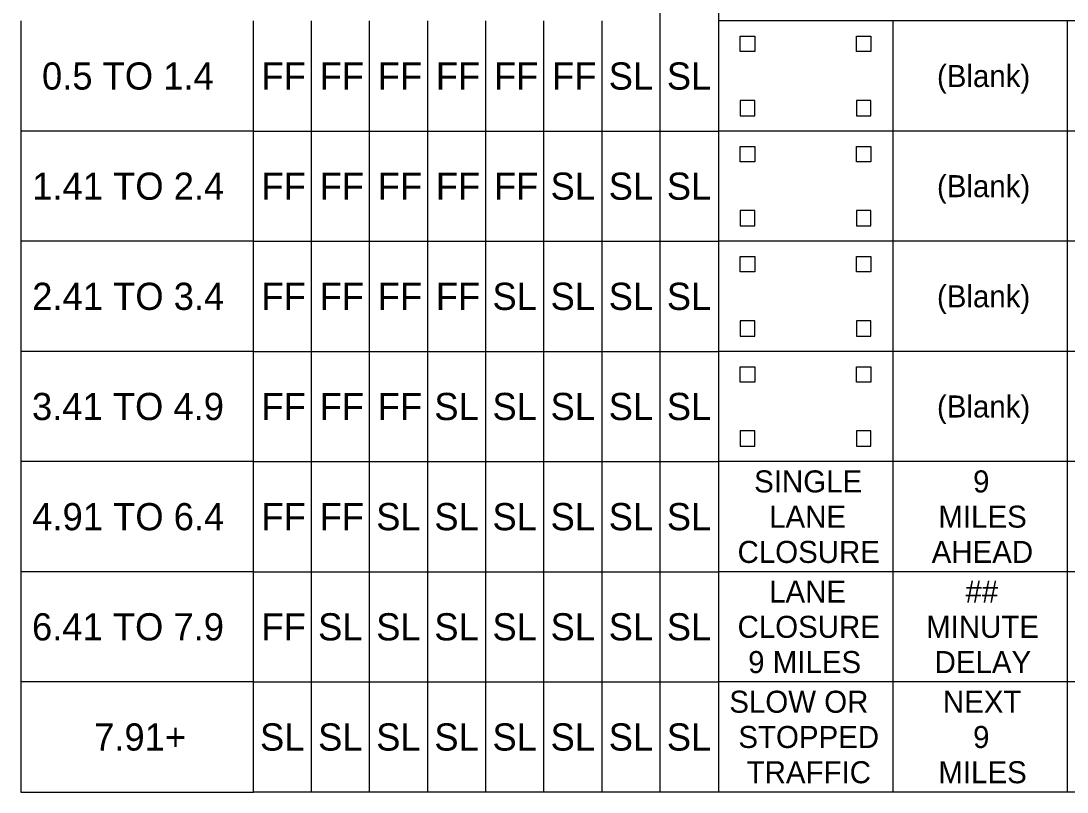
# Model space of a CAD drawing. Extents: x 99999.1 to 100055.7, y 99995 to 100017.5.
# Drawn here: x 100004.329 to 100007.417, y 100001.966 to 100004.241 of the extents above; entities that cross this region are included whole.
import ezdxf

# ---------------------------------------------------------------- set-up
doc = ezdxf.new("R2010")
doc.units = 0
doc.layers.add('TR_WZ_WorkZoneDetails', color=7, linetype='Continuous')
doc.layers.add('TR_WZ_WorkZoneTextCurrent', color=7, linetype='Continuous')

msp = doc.modelspace()

# ---------------------------------------------------------------- linework, layer by layer
at = {"layer": 'TR_WZ_WorkZoneDetails'}
for p, q in [((100004.3292, 100004.2408), (100004.3292, 100003.9158)), ((100005.0153, 100003.9158), (100005.0153, 100004.2408)), ((100005.1868, 100003.9158), (100005.1868, 100004.2408)), ((100005.1868, 100003.9158), (100005.1868, 100004.2408)), ((100005.3583, 100003.9158), (100005.3583, 100004.2408)), ((100005.3583, 100003.9158), (100005.3583, 100004.2408)), ((100005.5299, 100003.9158), (100005.5299, 100004.2408)), ((100005.7014, 100003.9158), (100005.7014, 100004.2408)), ((100005.8729, 100003.9158), (100005.8729, 100004.2408)), ((100006.0444, 100003.9158), (100006.0444, 100004.2408)), ((100006.216, 100003.9158), (100006.216, 100004.2408)), ((100006.3875, 100004.2408), (100006.3875, 100003.9158)), ((100007.4167, 100004.2408), (100006.3875, 100004.2408)), ((100006.9021, 100004.2408), (100006.9021, 100003.9158)), ((100008.4458, 100004.2408), (100007.4167, 100004.2408)), ((100007.4167, 100004.2408), (100007.4167, 100003.9158)), ((100005.0153, 100003.9158), (100004.3292, 100003.9158)), ((100004.3292, 100003.9158), (100004.3292, 100003.5908)), ((100005.0153, 100003.5908), (100005.0153, 100003.9158)), ((100005.0153, 100003.9158), (100005.1868, 100003.9158)), ((100005.1868, 100003.9158), (100005.3583, 100003.9158)), ((100005.1868, 100003.5908), (100005.1868, 100003.9158)), ((100005.1868, 100003.5908), (100005.1868, 100003.9158)), ((100005.3583, 100003.5908), (100005.3583, 100003.9158)), ((100005.3583, 100003.9158), (100005.5299, 100003.9158)), ((100005.3583, 100003.5908), (100005.3583, 100003.9158)), ((100005.5299, 100003.5908), (100005.5299, 100003.9158)), ((100005.5299, 100003.9158), (100005.7014, 100003.9158)), ((100005.7014, 100003.5908), (100005.7014, 100003.9158)), ((100005.7014, 100003.9158), (100005.8729, 100003.9158)), ((100005.8729, 100003.5908), (100005.8729, 100003.9158)), ((100005.8729, 100003.9158), (100006.0444, 100003.9158)), ((100006.0444, 100003.5908), (100006.0444, 100003.9158)), ((100006.0444, 100003.9158), (100006.216, 100003.9158)), ((100006.216, 100003.5908), (100006.216, 100003.9158)), ((100006.216, 100003.9158), (100006.3875, 100003.9158)), ((100006.3875, 100003.9158), (100006.3875, 100003.5908)), ((100007.4167, 100003.9158), (100006.3875, 100003.9158)), ((100006.9021, 100003.9158), (100006.9021, 100003.5908)), ((100008.4458, 100003.9158), (100007.4167, 100003.9158)), ((100007.4167, 100003.9158), (100007.4167, 100003.5908)), ((100005.0153, 100003.5908), (100004.3292, 100003.5908)), ((100004.3292, 100003.5908), (100004.3292, 100003.2658)), ((100005.0153, 100003.2658), (100005.0153, 100003.5908)), ((100005.0153, 100003.5908), (100005.1868, 100003.5908)), ((100005.1868, 100003.5908), (100005.3583, 100003.5908)), ((100005.1868, 100003.2658), (100005.1868, 100003.5908)), ((100005.1868, 100003.2658), (100005.1868, 100003.5908)), ((100005.3583, 100003.2658), (100005.3583, 100003.5908)), ((100005.3583, 100003.5908), (100005.5299, 100003.5908)), ((100005.3583, 100003.2658), (100005.3583, 100003.5908)), ((100005.5299, 100003.2658), (100005.5299, 100003.5908)), ((100005.5299, 100003.5908), (100005.7014, 100003.5908)), ((100005.7014, 100003.2658), (100005.7014, 100003.5908)), ((100005.7014, 100003.5908), (100005.8729, 100003.5908)), ((100005.8729, 100003.2658), (100005.8729, 100003.5908)), ((100005.8729, 100003.5908), (100006.0444, 100003.5908)), ((100006.0444, 100003.2658), (100006.0444, 100003.5908)), ((100006.0444, 100003.5908), (100006.216, 100003.5908)), ((100006.216, 100003.2658), (100006.216, 100003.5908)), ((100006.216, 100003.5908), (100006.3875, 100003.5908)), ((100006.3875, 100003.5908), (100006.3875, 100003.2658)), ((100007.4167, 100003.5908), (100006.3875, 100003.5908)), ((100006.9021, 100003.5908), (100006.9021, 100003.2658)), ((100008.4458, 100003.5908), (100007.4167, 100003.5908)), ((100007.4167, 100003.5908), (100007.4167, 100003.2658)), ((100005.0153, 100003.2658), (100004.3292, 100003.2658)), ((100004.3292, 100003.2658), (100004.3292, 100002.9408)), ((100005.0153, 100002.9408), (100005.0153, 100003.2658)), ((100005.0153, 100003.2658), (100005.1868, 100003.2658)), ((100005.1868, 100003.2658), (100005.3583, 100003.2658)), ((100005.1868, 100002.9408), (100005.1868, 100003.2658)), ((100005.1868, 100002.9408), (100005.1868, 100003.2658)), ((100005.3583, 100002.9408), (100005.3583, 100003.2658)), ((100005.3583, 100003.2658), (100005.5299, 100003.2658)), ((100005.3583, 100002.9408), (100005.3583, 100003.2658)), ((100005.5299, 100002.9408), (100005.5299, 100003.2658)), ((100005.5299, 100003.2658), (100005.7014, 100003.2658)), ((100005.7014, 100002.9408), (100005.7014, 100003.2658)), ((100005.7014, 100003.2658), (100005.8729, 100003.2658)), ((100005.8729, 100002.9408), (100005.8729, 100003.2658)), ((100005.8729, 100003.2658), (100006.0444, 100003.2658)), ((100006.0444, 100002.9408), (100006.0444, 100003.2658)), ((100006.0444, 100003.2658), (100006.216, 100003.2658)), ((100006.216, 100002.9408), (100006.216, 100003.2658)), ((100006.216, 100003.2658), (100006.3875, 100003.2658)), ((100006.3875, 100003.2658), (100006.3875, 100002.9408)), ((100007.4167, 100003.2658), (100006.3875, 100003.2658)), ((100006.9021, 100003.2658), (100006.9021, 100002.9408)), ((100008.4458, 100003.2658), (100007.4167, 100003.2658)), ((100007.4167, 100003.2658), (100007.4167, 100002.9408)), ((100005.0153, 100002.9408), (100004.3292, 100002.9408)), ((100004.3292, 100002.9408), (100004.3292, 100002.6158)), ((100005.0153, 100002.6158), (100005.0153, 100002.9408)), ((100005.0153, 100002.9408), (100005.1868, 100002.9408)), ((100005.1868, 100002.9408), (100005.3583, 100002.9408)), ((100005.1868, 100002.6158), (100005.1868, 100002.9408)), ((100005.1868, 100002.6158), (100005.1868, 100002.9408)), ((100005.3583, 100002.6158), (100005.3583, 100002.9408)), ((100005.3583, 100002.9408), (100005.5299, 100002.9408)), ((100005.3583, 100002.6158), (100005.3583, 100002.9408)), ((100005.5299, 100002.6158), (100005.5299, 100002.9408)), ((100005.5299, 100002.9408), (100005.7014, 100002.9408)), ((100005.7014, 100002.6158), (100005.7014, 100002.9408)), ((100005.7014, 100002.9408), (100005.8729, 100002.9408)), ((100005.8729, 100002.6158), (100005.8729, 100002.9408)), ((100005.8729, 100002.9408), (100006.0444, 100002.9408)), ((100006.0444, 100002.6158), (100006.0444, 100002.9408)), ((100006.0444, 100002.9408), (100006.216, 100002.9408)), ((100006.216, 100002.6158), (100006.216, 100002.9408)), ((100006.216, 100002.9408), (100006.3875, 100002.9408)), ((100006.3875, 100002.9408), (100006.3875, 100002.6158)), ((100007.4167, 100002.9408), (100006.3875, 100002.9408)), ((100006.9021, 100002.9408), (100006.9021, 100002.6158)), ((100008.4458, 100002.9408), (100007.4167, 100002.9408)), ((100007.4167, 100002.9408), (100007.4167, 100002.6158)), ((100005.0153, 100002.6158), (100004.3292, 100002.6158)), ((100005.0153, 100002.6158), (100004.3292, 100002.6158)), ((100004.3292, 100002.6158), (100004.3292, 100002.2908)), ((100005.0153, 100002.6158), (100005.1868, 100002.6158)), ((100005.0153, 100002.2908), (100005.0153, 100002.6158)), ((100005.0153, 100002.6158), (100005.1868, 100002.6158)), ((100005.1868, 100002.6158), (100005.3583, 100002.6158)), ((100005.1868, 100002.6158), (100005.3583, 100002.6158)), ((100005.1868, 100002.2908), (100005.1868, 100002.6158)), ((100005.1868, 100002.2908), (100005.1868, 100002.6158)), ((100005.3583, 100002.6158), (100005.5299, 100002.6158)), ((100005.3583, 100002.2908), (100005.3583, 100002.6158)), ((100005.3583, 100002.6158), (100005.5299, 100002.6158)), ((100005.3583, 100002.2908), (100005.3583, 100002.6158)), ((100005.5299, 100002.6158), (100005.7014, 100002.6158)), ((100005.5299, 100002.2908), (100005.5299, 100002.6158)), ((100005.5299, 100002.6158), (100005.7014, 100002.6158)), ((100005.7014, 100002.6158), (100005.8729, 100002.6158)), ((100005.7014, 100002.2908), (100005.7014, 100002.6158)), ((100005.7014, 100002.6158), (100005.8729, 100002.6158)), ((100005.8729, 100002.6158), (100006.0444, 100002.6158)), ((100005.8729, 100002.2908), (100005.8729, 100002.6158)), ((100005.8729, 100002.6158), (100006.0444, 100002.6158)), ((100006.0444, 100002.6158), (100006.216, 100002.6158)), ((100006.0444, 100002.2908), (100006.0444, 100002.6158)), ((100006.0444, 100002.6158), (100006.216, 100002.6158)), ((100006.216, 100002.6158), (100006.3875, 100002.6158)), ((100006.216, 100002.2908), (100006.216, 100002.6158)), ((100006.216, 100002.6158), (100006.3875, 100002.6158)), ((100007.4167, 100002.6158), (100006.3875, 100002.6158)), ((100006.3875, 100002.6158), (100006.3875, 100002.2908)), ((100007.4167, 100002.6158), (100006.3875, 100002.6158)), ((100006.9021, 100002.6158), (100006.9021, 100002.2908)), ((100008.4458, 100002.6158), (100007.4167, 100002.6158)), ((100008.4458, 100002.6158), (100007.4167, 100002.6158)), ((100007.4167, 100002.6158), (100007.4167, 100002.2908)), ((100004.3292, 100002.2908), (100004.3292, 100001.9658)), ((100005.0153, 100002.2908), (100004.3292, 100002.2908)), ((100005.0153, 100001.9658), (100005.0153, 100002.2908)), ((100005.0153, 100002.2908), (100005.1868, 100002.2908)), ((100005.1868, 100001.9658), (100005.1868, 100002.2908)), ((100005.1868, 100001.9658), (100005.1868, 100002.2908)), ((100005.1868, 100002.2908), (100005.3583, 100002.2908)), ((100005.3583, 100001.9658), (100005.3583, 100002.2908)), ((100005.3583, 100001.9658), (100005.3583, 100002.2908)), ((100005.3583, 100002.2908), (100005.5299, 100002.2908)), ((100005.5299, 100001.9658), (100005.5299, 100002.2908)), ((100005.5299, 100002.2908), (100005.7014, 100002.2908)), ((100005.7014, 100001.9658), (100005.7014, 100002.2908)), ((100005.7014, 100002.2908), (100005.8729, 100002.2908)), ((100005.8729, 100001.9658), (100005.8729, 100002.2908)), ((100005.8729, 100002.2908), (100006.0444, 100002.2908)), ((100006.0444, 100001.9658), (100006.0444, 100002.2908)), ((100006.0444, 100002.2908), (100006.216, 100002.2908)), ((100006.216, 100001.9658), (100006.216, 100002.2908)), ((100006.216, 100002.2908), (100006.3875, 100002.2908)), ((100006.3875, 100002.2908), (100006.3875, 100001.9658)), ((100007.4167, 100002.2908), (100006.3875, 100002.2908)), ((100006.9021, 100002.2908), (100006.9021, 100001.9658)), ((100007.4167, 100002.2908), (100007.4167, 100001.9658)), ((100008.4458, 100002.2908), (100007.4167, 100002.2908)), ((100004.3292, 100001.9658), (100005.0153, 100001.9658)), ((100005.1868, 100001.9658), (100005.0153, 100001.9658)), ((100005.3583, 100001.9658), (100005.1868, 100001.9658)), ((100005.5299, 100001.9658), (100005.3583, 100001.9658)), ((100005.7014, 100001.9658), (100005.5299, 100001.9658)), ((100005.8729, 100001.9658), (100005.7014, 100001.9658)), ((100006.0444, 100001.9658), (100005.8729, 100001.9658)), ((100006.216, 100001.9658), (100006.0444, 100001.9658)), ((100006.3875, 100001.9658), (100006.216, 100001.9658)), ((100007.4167, 100001.9658), (100006.3875, 100001.9658)), ((100008.4458, 100001.9658), (100007.4167, 100001.9658))]:
    msp.add_line(p, q, dxfattribs=at)
msp.add_lwpolyline([(100006.216, 100004.8908), (100006.3875, 100004.8908), (100006.3875, 100001.9658), (100006.216, 100001.9658)], close=True, dxfattribs=at)
at = {"layer": 'TR_WZ_WorkZoneTextCurrent'}
for points in [[(100006.4518, 100004.1956), (100006.4947, 100004.1956), (100006.4947, 100004.1505), (100006.4518, 100004.1505)], [(100006.7949, 100004.1956), (100006.8378, 100004.1956), (100006.8378, 100004.1505), (100006.7949, 100004.1505)], [(100006.4518, 100003.9609), (100006.4947, 100003.9609), (100006.4947, 100004.0061), (100006.4518, 100004.0061)], [(100006.7949, 100003.9609), (100006.8378, 100003.9609), (100006.8378, 100004.0061), (100006.7949, 100004.0061)], [(100006.4518, 100003.8706), (100006.4947, 100003.8706), (100006.4947, 100003.8255), (100006.4518, 100003.8255)], [(100006.7949, 100003.8706), (100006.8378, 100003.8706), (100006.8378, 100003.8255), (100006.7949, 100003.8255)], [(100006.4518, 100003.6359), (100006.4947, 100003.6359), (100006.4947, 100003.6811), (100006.4518, 100003.6811)], [(100006.7949, 100003.6359), (100006.8378, 100003.6359), (100006.8378, 100003.6811), (100006.7949, 100003.6811)], [(100006.4518, 100003.5456), (100006.4947, 100003.5456), (100006.4947, 100003.5005), (100006.4518, 100003.5005)], [(100006.7949, 100003.5456), (100006.8378, 100003.5456), (100006.8378, 100003.5005), (100006.7949, 100003.5005)], [(100006.4518, 100003.3109), (100006.4947, 100003.3109), (100006.4947, 100003.3561), (100006.4518, 100003.3561)], [(100006.7949, 100003.3109), (100006.8378, 100003.3109), (100006.8378, 100003.3561), (100006.7949, 100003.3561)], [(100006.4518, 100003.2206), (100006.4947, 100003.2206), (100006.4947, 100003.1755), (100006.4518, 100003.1755)], [(100006.7949, 100003.2206), (100006.8378, 100003.2206), (100006.8378, 100003.1755), (100006.7949, 100003.1755)], [(100006.4518, 100002.9859), (100006.4947, 100002.9859), (100006.4947, 100003.0311), (100006.4518, 100003.0311)], [(100006.7949, 100002.9859), (100006.8378, 100002.9859), (100006.8378, 100003.0311), (100006.7949, 100003.0311)]]:
    msp.add_lwpolyline(points, close=True, dxfattribs=at)

# ---------------------------------------------------------------- texts
for s, height, p in [('0.5 TO 1.4', 0.08025, (100004.3913, 100004.0382)), ('FF', 0.08025, (100005.039, 100004.0382)), ('FF', 0.08025, (100005.2105, 100004.0382)), ('FF', 0.08025, (100005.3821, 100004.0382)), ('FF', 0.08025, (100005.5536, 100004.0382)), ('FF', 0.08025, (100005.7251, 100004.0382)), ('FF', 0.08025, (100005.8966, 100004.0382)), ('SL', 0.08025, (100006.0638, 100004.0382)), ('SL', 0.08025, (100006.2354, 100004.0382)), ('(Blank)', 0.065, (100007.0327, 100004.0458)), ('1.41 TO 2.4', 0.080247, (100004.3625, 100003.7132)), ('FF', 0.08025, (100005.039, 100003.7132)), ('FF', 0.08025, (100005.2105, 100003.7132)), ('FF', 0.08025, (100005.3821, 100003.7132)), ('FF', 0.08025, (100005.5536, 100003.7132)), ('FF', 0.08025, (100005.7251, 100003.7132)), ('SL', 0.08025, (100005.8923, 100003.7132)), ('SL', 0.08025, (100006.0638, 100003.7132)), ('SL', 0.08025, (100006.2354, 100003.7132)), ('(Blank)', 0.065, (100007.0327, 100003.7208)), ('2.41 TO 3.4', 0.080247, (100004.3625, 100003.3882)), ('FF', 0.08025, (100005.039, 100003.3882)), ('FF', 0.08025, (100005.2105, 100003.3882)), ('FF', 0.08025, (100005.3821, 100003.3882)), ('FF', 0.08025, (100005.5536, 100003.3882)), ('SL', 0.08025, (100005.7208, 100003.3882)), ('SL', 0.08025, (100005.8923, 100003.3882)), ('SL', 0.08025, (100006.0638, 100003.3882)), ('SL', 0.08025, (100006.2354, 100003.3882)), ('(Blank)', 0.065, (100007.0327, 100003.3958)), ('3.41 TO 4.9', 0.080247, (100004.3618, 100003.0632)), ('FF', 0.08025, (100005.039, 100003.0632)), ('FF', 0.08025, (100005.2105, 100003.0632)), ('FF', 0.08025, (100005.3821, 100003.0632)), ('SL', 0.08025, (100005.5492, 100003.0632)), ('SL', 0.08025, (100005.7208, 100003.0632)), ('SL', 0.08025, (100005.8923, 100003.0632)), ('SL', 0.08025, (100006.0638, 100003.0632)), ('SL', 0.08025, (100006.2354, 100003.0632)), ('(Blank)', 0.065, (100007.0327, 100003.0708)), ('SINGLE', 0.065, (100006.4931, 100002.8498)), ('9', 0.065, (100007.1393, 100002.8498)), ('4.91 TO 6.4', 0.080247, (100004.3625, 100002.7382)), ('FF', 0.08025, (100005.039, 100002.7382)), ('FF', 0.08025, (100005.2105, 100002.7382)), ('SL', 0.08025, (100005.3777, 100002.7382)), ('SL', 0.08025, (100005.5492, 100002.7382)), ('SL', 0.08025, (100005.7208, 100002.7382)), ('SL', 0.08025, (100005.8923, 100002.7382)), ('SL', 0.08025, (100006.0638, 100002.7382)), ('SL', 0.08025, (100006.2354, 100002.7382)), ('LANE', 0.065, (100006.5373, 100002.7458)), ('MILES', 0.065, (100007.0368, 100002.7458)), ('CLOSURE', 0.065, (100006.4442, 100002.6418)), ('AHEAD', 0.065, (100007.017, 100002.6418)), ('LANE', 0.065, (100006.5373, 100002.5248)), ('##', 0.065, (100007.1166, 100002.5248)), ('6.41 TO 7.9', 0.080247, (100004.3618, 100002.4132)), ('FF', 0.08025, (100005.039, 100002.4132)), ('SL', 0.08025, (100005.2062, 100002.4132)), ('SL', 0.08025, (100005.3777, 100002.4132)), ('SL', 0.08025, (100005.5492, 100002.4132)), ('SL', 0.08025, (100005.7208, 100002.4132)), ('SL', 0.08025, (100005.8923, 100002.4132)), ('SL', 0.08025, (100006.0638, 100002.4132)), ('SL', 0.08025, (100006.2354, 100002.4132)), ('CLOSURE', 0.065, (100006.4442, 100002.4208)), ('MINUTE', 0.065, (100007.0007, 100002.4208)), ('9 MILES', 0.065, (100006.4755, 100002.3168)), ('DELAY', 0.065, (100007.0257, 100002.3168)), ('SLOW OR', 0.065, (100006.4198, 100002.1998)), ('NEXT', 0.065, (100007.0502, 100002.1998)), ('7.91+', 0.08025, (100004.5452, 100002.0882)), ('SL', 0.08025, (100005.0347, 100002.0882)), ('SL', 0.08025, (100005.2062, 100002.0882)), ('SL', 0.08025, (100005.3777, 100002.0882)), ('SL', 0.08025, (100005.5492, 100002.0882)), ('SL', 0.08025, (100005.7208, 100002.0882)), ('SL', 0.08025, (100005.8923, 100002.0882)), ('SL', 0.08025, (100006.0638, 100002.0882)), ('SL', 0.08025, (100006.2354, 100002.0882)), ('STOPPED', 0.065, (100006.4465, 100002.0958)), ('9', 0.065, (100007.1393, 100002.0958)), ('TRAFFIC', 0.065, (100006.471, 100001.9918)), ('MILES', 0.065, (100007.0368, 100001.9918))]:
    msp.add_text(s, height=height, rotation=360, dxfattribs=at).set_placement(p)

doc.saveas('drawing.dxf')
